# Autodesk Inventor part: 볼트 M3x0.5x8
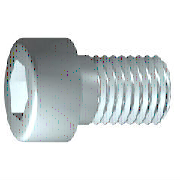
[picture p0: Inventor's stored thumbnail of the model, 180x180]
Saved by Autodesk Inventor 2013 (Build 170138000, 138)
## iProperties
IsCustomPart: 1
Company: 한국ATC센터
Created: 2015-12
Part Number: 볼트 M3x0.5x8
Material: 스테인리스강
Description: 6각머리 태핑 나사
Document SubType Name: Modeling
Standard: KS B 1003
Designer: mdu
Standards Organization: KS
Language: ko-KR
Size Designation: M 4 x 12
Categories: <MemberInstance><Categories><Category DisplayName="조임쇠" InternalName="e4da775c-781d-43d5-af7c-5136215cf5a6" Mnemonic="FSTN"><Category DisplayName="볼트" InternalN
Density: 8.08 g/cm^3
Mass: 1.41278 g
Surface Area: 2.58399 cm^2
Volume: 0.174849 cm^3
Author: mdu
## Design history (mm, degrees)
sketch "스케치1"
  geometry: L1 (-0.867, 0)-(16, 0); L2 (16, 0)-(16, 1.5); L3 (16, 1.5)-(1.25, 1.5); L4 (1.25, 1.5)-(0.943, 1.5); L5 (0.943, 1.5)-(0, 1.5); L6 (0, 1.5)-(0, 2.75); L7 (0, 2.75)-(-3, 2.75); L8 (-3, 2.75)-(-3, 1.443); L9 (-3, 1.443)-(-1.7, 1.443); L10 (-1.7, 1.443)-(-0.867, 0); L11 (-6.8, 0)-(19.8, 0) reference; L12 (0, -0.55)-(0, 3.3) reference; L13 (1.25, 1.5)-(0, 1.5)
  constraints: 22 end point, 6 parallel, 2 collinear, 2 perpendicular, 1 horizontal, 1 point on line
  dimensions: "d1" = 14.75 distance from line of L3.end L2 (= GEL); "d2" = 0.30683 distance of L4.end L3.end (computed from GAL); "d3" = 3 distance between parallel lines of L8 L6 (= KOH); "d4" = 1.3 distance of L8.end L9.end (= INTI); "d5" = 60 deg angle of L10 L1; "d6" = 3 diameter of L3 L1 (= GD); "d7" = 3 diameter of L5 L1 (= BDM); "d8" = 2.88675 diameter of L9 L1 (= 1.1547 x SW); "d9" = 5.5 diameter of L7 L1 (= KOD); "d26" = 16 distance between parallel lines of L12 L2 (= NLG)
revolve "본체" sketch "스케치1" stored, may be unused: angle "d10" = 90 deg
sketch "스케치2"
  geometry: L1 (0, -3.85)-(0, 3.85) reference; L2 (-3.85, 0)-(3.85, 0) reference; L3 (1.443, 0)-(0.722, -1.25); L4 (0.722, -1.25)-(-0.722, -1.25); L5 (-0.722, -1.25)-(-1.443, 0); L6 (-1.443, 0)-(-0.722, 1.25); L7 (-0.722, 1.25)-(0.722, 1.25); L8 (0.722, 1.25)-(1.443, 0); 2 further points
  constraints: 12 end point, 1 coincident, 1 horizontal alignment, 1 point on line, 12 other
extrude "슬롯" join sketch "스케치2" stored distance "d11" = 10; taper "d12" = 0 deg
workplane "Work Plane1"
fillet "Fillet2" dims "d30" = 0.1 (= R)
body "Solid1"
fillet "모깎기1" dims "d17" = 0.3 (= RR)
feature "스레드" dims "d13" = 14.75 (= GEL), "d14" = 0
chamfer "모따기1" distance "d15" = 0.30673 (= -0.5 x SPD + 0.5 x GD); stored, may be unused: second distance "d16" = 0.30673 (= GUL), angle "d27" = 45 deg
other parameters: "GD" = 3 (= NND) [user parameter; used in 2 equation terms], "NLG" = 16 [user parameter; used in 1 equation term], "GEL" = 14.75 [user parameter; used in 2 equation terms], "KOD" = 5.5 [user parameter; used in 1 equation term], "KOH" = 3 [user parameter; used in 1 equation term], "INTI" = 1.3 [user parameter; used in 1 equation term], "GAL" = 0.30673 (= 0.61345 x PTC) [user parameter; used in 1 equation term], "GUL" = 0.30673 (= 0.61345 x PTC) [user parameter; used in 1 equation term], "BDM" = 3 (= NND) [user parameter; used in 1 equation term], "SW" = 2.5 [user parameter; used in 2 equation terms], "RR" = 0.3 [user parameter; used in 1 equation term], "SPD" = 2.38655 (= NND - 1.2269 x PTC) [user parameter; used in 1 equation term], "d19" = 0, "d28" = 0, "d29" = 0, "R" = 0.1 [user parameter; used in 1 equation term], "PHH" = 0.1 [user parameter], "GD1" = 2.38655 (= THREADDIA - 1.2269 x PTC) [user parameter], "THREADDIA" = 3 [user parameter; used in 1 equation term], "FAWI" = 45 deg [user parameter], "PTC" = 0.5 [user parameter; used in 5 equation terms], "NND" = 3 [user parameter; used in 3 equation terms], "TOA" = 30 deg [user parameter], "E0" = 2.8875 (= 1.155 x SW) [user parameter]
